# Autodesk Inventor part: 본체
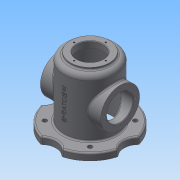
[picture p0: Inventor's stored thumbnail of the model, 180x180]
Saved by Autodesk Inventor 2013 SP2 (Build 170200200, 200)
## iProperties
Created: 2026-07
Part Number: 본체
Material: Generic
Document SubType Name: Modeling
Designer: aa
Density: 1 g/cm^3
Author: aa
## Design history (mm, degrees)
sketch "스케치1"
  geometry: C1 r 82 at (0, 0); 1 further point
  constraints: 1 centre point, 1 coincident
  dimensions: "d0" = 164 diameter of C1
extrude "돌출1" new body sketch "스케치1" distance "d1" = 14; taper "d2" = 0 deg
sketch "스케치2"
  geometry: C1 r 82 at (0, 0) reference; C2 r 30 at (-100, 0); C3 r 30 at (0, -100); C4 r 30 at (100, 0); C5 r 30 at (0, 100)
  constraints: 4 centre point, 1 horizontal alignment, 9 other
  dimensions: "d3" = 60 diameter of C2; "d4" = 100 distance of C1.centre C2.centre; "d7" = 360 deg dimension on C1.centre C2.centre (derived)
extrude "돌출2" cut sketch "스케치2" distance "d9" = 14; taper "d10" = 0 deg
sketch "스케치3"
  geometry: C1 r 53 at (0, 0); A1 r 82 centre (0, 0) between (-21.541, 79.12) and (-79.12, 21.541) reference
  constraints: 1 centre point, 1 coincident
  dimensions: "d11" = 106 diameter of C1
extrude "돌출3" join sketch "스케치3" distance "d12" = 118; taper "d13" = 0 deg
sketch "스케치4"
  geometry: C1 r 53 at (0, 0) reference; C2 r 40 at (0, 0); 1 further point
  constraints: 1 centre point, 1 coincident
  dimensions: "d14" = 80 diameter of C2
extrude "돌출4" join sketch "스케치4" distance "d15" = 5; taper "d16" = 0 deg
sketch "스케치5"
  geometry: C1 r 45 at (0, 0); A1 r 82 centre (0, 0) between (-21.541, 79.12) and (-79.12, 21.541) reference
  constraints: 1 centre point, 1 coincident
  dimensions: "d17" = 90 diameter of C1
extrude "돌출5" cut sketch "스케치5" distance "d18" = 124; taper "d19" = 0 deg
sketch "스케치6"
  geometry: C1 r 40 at (0, 0) reference; C2 r 27 at (0, 0)
  constraints: 1 centre point, 1 coincident
  dimensions: "d20" = 54 diameter of C2
extrude "돌출6" cut sketch "스케치6" stored distance "d21" = 124; taper "d22" = 0 deg
fillet "모깎기1" dims "d23" = 10
fillet "모깎기2" dims "d24" = 3
chamfer "모따기1" distance "d25" = 1; stored, may be unused: second distance "d26" = 2, angle "d27" = 45 deg
sketch "스케치7"
  geometry: C1 r 40 at (0, 0) reference; 1 further point
  constraints: 1 vertical alignment
  dimensions: "d28" = 32.5 distance of C1.centre point (0, 32.5)
hole "구멍1" sketch "스케치7" at (0, 32.5) diameter "d29" = 3.242; stored, may be unused: countersink angle "d33" = 90 deg, drill point angle "d35" = 118 deg; dims "d30" = 8, "d31" = 4, "d32" = 2, "d34" = 10
sketch "스케치8" dims "d40" = 135
  geometry: L1 (0, 100)-(0, -100); L2 (-46.554, 46.554)-(0, 0); A1 r 30 centre (0, 100) between (-21.541, 79.12) and (21.541, 79.12) reference; A2 r 30 centre (0, -100) between (21.541, -79.12) and (-21.541, -79.12) reference; A3 r 82 centre (0, 0) between (79.12, 21.541) and (21.541, 79.12) reference; 2 further points
  constraints: 4 end point, 2 point on line, 1 midpoint, 1 vertical, 3 other
  dimensions: "d39" = 45 deg angle of L2 L1
hole "구멍2" sketch "스케치8" at (-46.554, 46.554) diameter "d41" = 9; stored, may be unused: countersink angle "d45" = 90 deg, drill point angle "d47" = 118 deg; dims "d42" = 8, "d43" = 4, "d44" = 2, "d46" = 10
node "작업 평면1"
sketch "스케치9"
  geometry: L1 (21.541, 0)-(-21.541, 0) reference; C1 r 40 at (0, 68); 2 further points
  constraints: 1 centre point, 1 midpoint, 1 vertical alignment
  dimensions: "d52" = 80 diameter of C1; "d53" = 68 distance from line of C1.centre L1
extrude "돌출7" join sketch "스케치9" stored distance "d54" = 124; taper "d55" = 0 deg
sketch "스케치10"
  geometry: C1 r 40 at (0, 0) reference; C2 r 27 at (0, 0); 1 further point
  constraints: 1 centre point, 1 coincident
  dimensions: "d57" = 54 diameter of C2
extrude "돌출8" cut sketch "스케치10" distance "d58" = 124; taper "d59" = 0 deg
fillet "모깎기3" dims "d60" = 3
sketch "스케치11"
  geometry: C1 r 27 at (0, 0) reference; 2 further points
  constraints: 1 horizontal alignment
  dimensions: "d61" = 32.5 distance of C1.centre point (-32.5, 0)
hole "구멍3" sketch "스케치11" at (-32.5, 0) diameter "d62" = 3.242; stored, may be unused: countersink angle "d66" = 90 deg, drill point angle "d68" = 118 deg; dims "d63" = 8, "d64" = 4, "d65" = 2, "d67" = 10
fillet "모깎기4" dims "d72" = 3
chamfer "모따기2" distance "d73" = 1; stored, may be unused: second distance "d74" = 2, angle "d75" = 45 deg
fillet "모깎기5" dims "d76" = 3
node "작업 평면2"
sketch "스케치14"
  geometry: L1 (20.357, 0)-(-20.357, 0) reference; 3 further points
  constraints: 1 midpoint, 1 vertical alignment, 1 other
  dimensions: "d79" = 70 distance from line of point (0, 70) L1
feature "엠보싱1" sketch "스케치14" dims "d1" = 14, "d80" = 0.5, "d81" = 0
node "솔리드1"
pattern_circular "원형 패턴1" dims angle "d37" = 360 deg
pattern_circular "원형 패턴2" dims angle "d49" = 360 deg
mirror "대칭1"
pattern_circular "원형 패턴3" dims angle "d70" = 360 deg
mirror "대칭2"
other parameters: "d51" = 62, "d77" = 53.5
